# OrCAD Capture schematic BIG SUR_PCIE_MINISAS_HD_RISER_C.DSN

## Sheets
1 03.MINI SAS HD CONN: size C; title: Big Sur; rev: C; company: Quanta
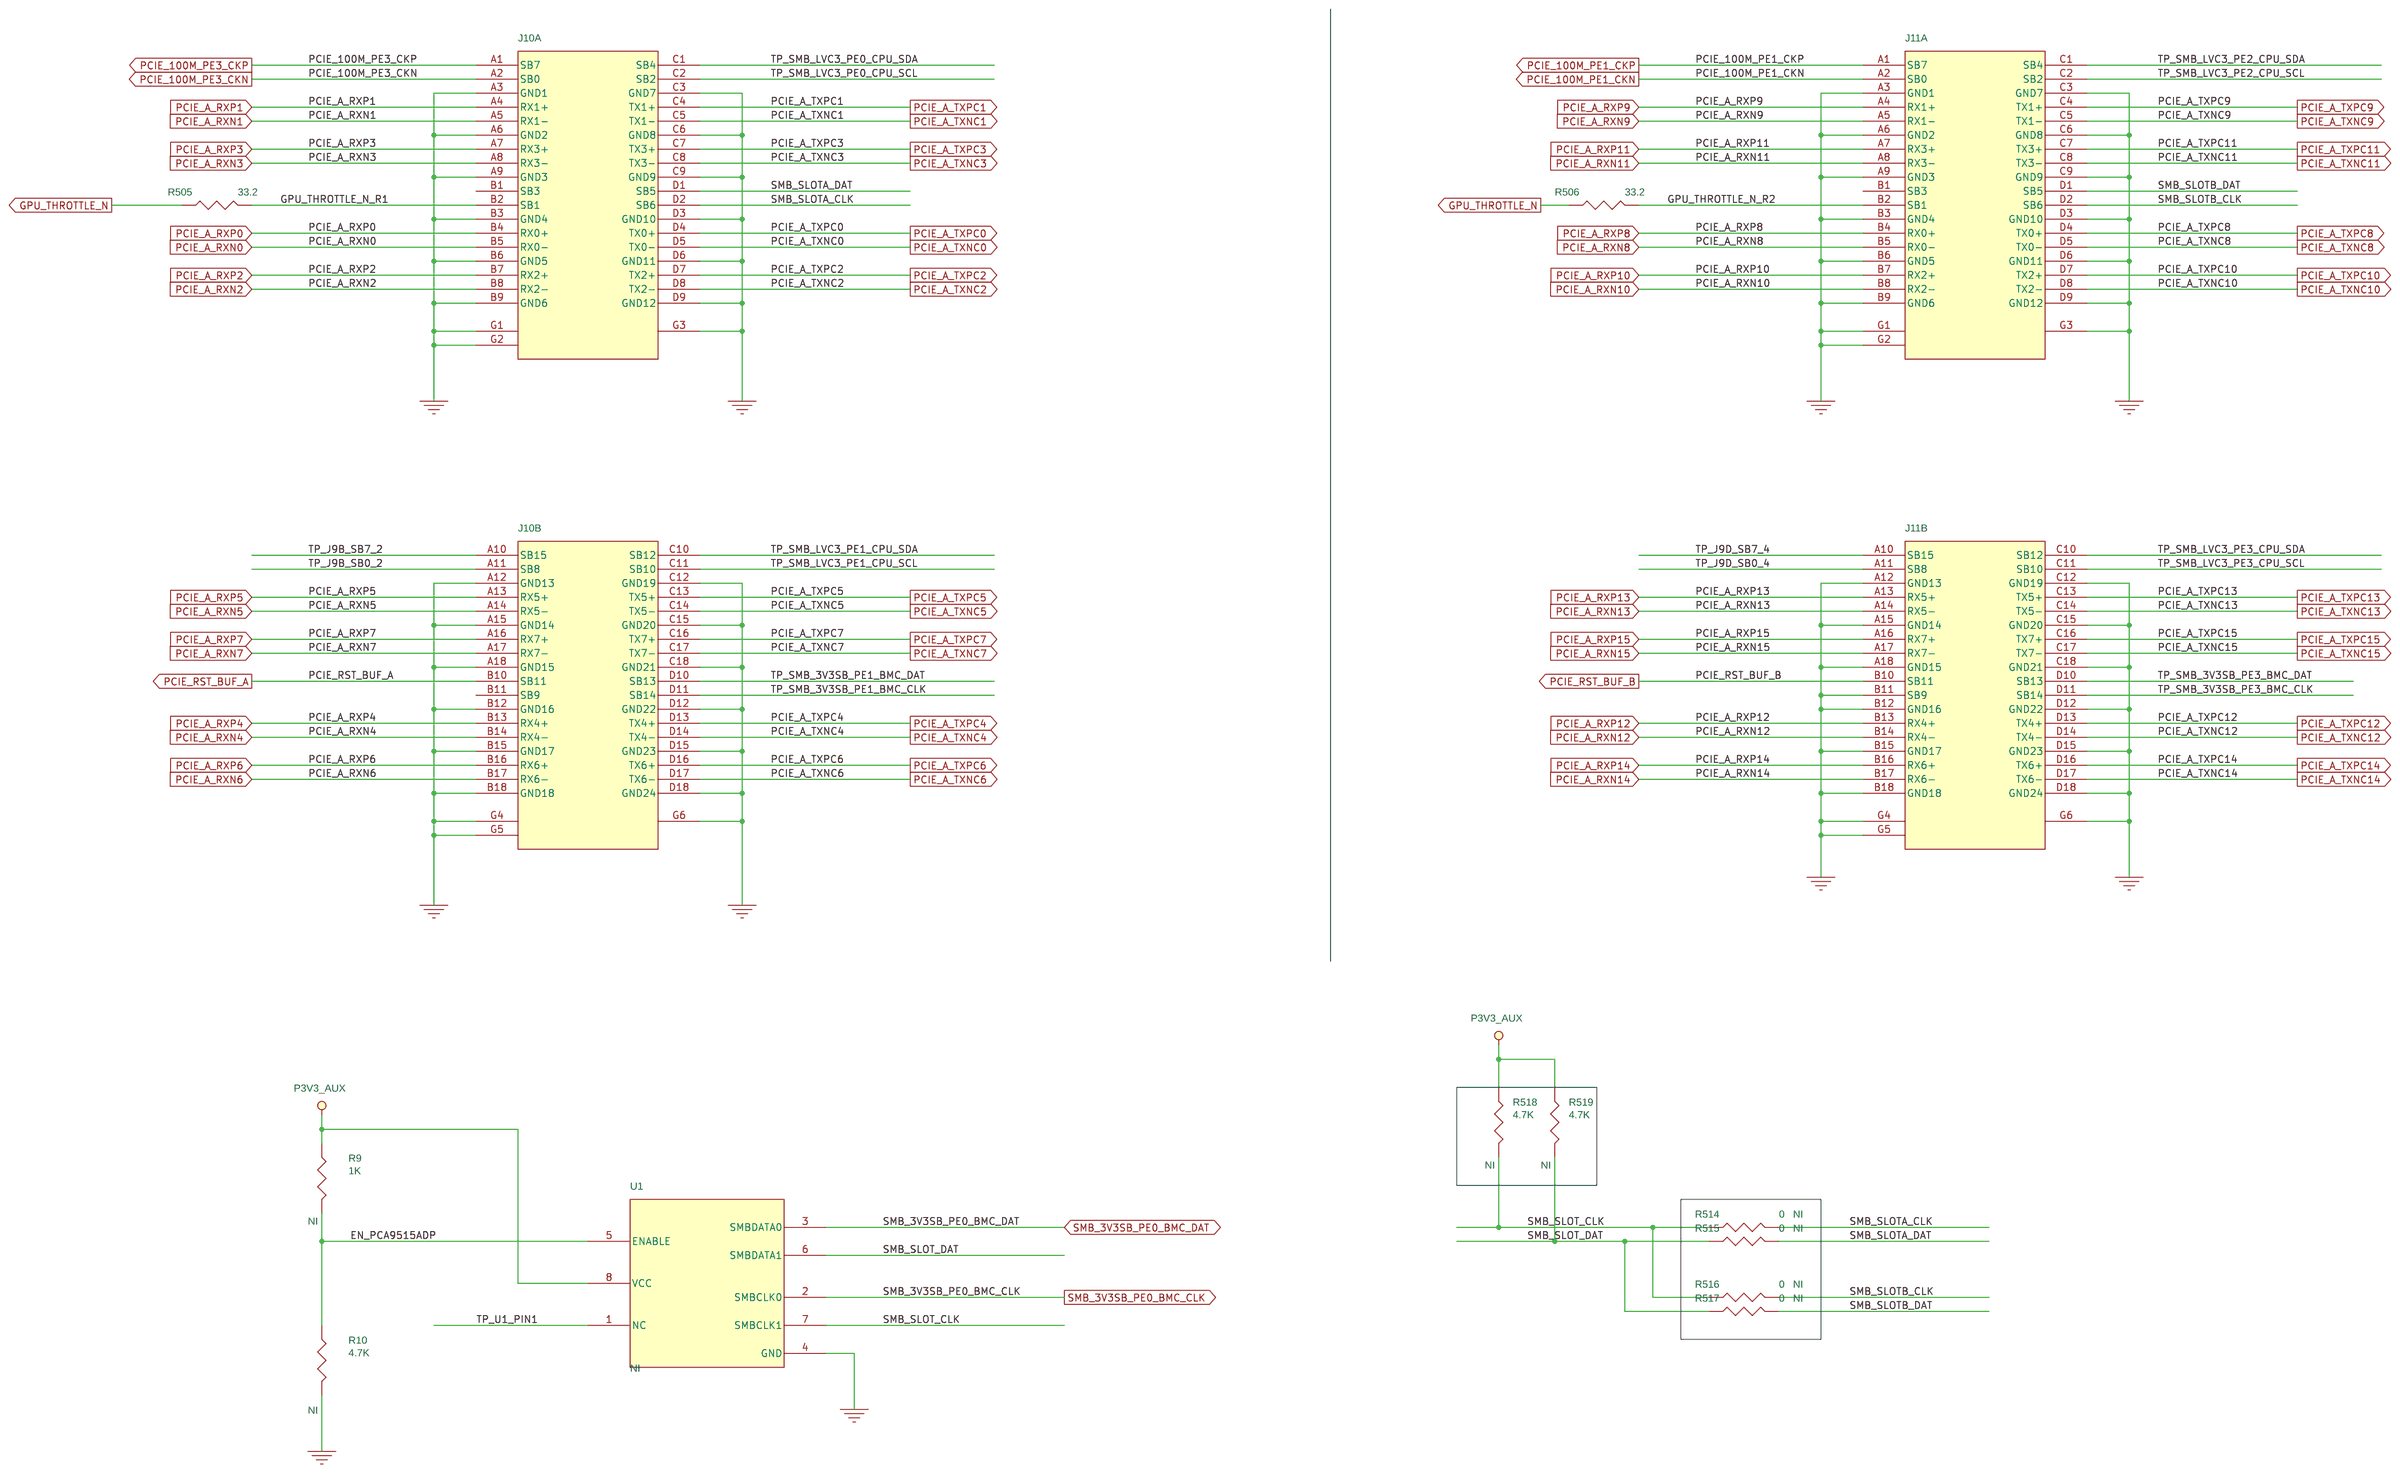
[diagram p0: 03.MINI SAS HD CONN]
2 01.Cover Page
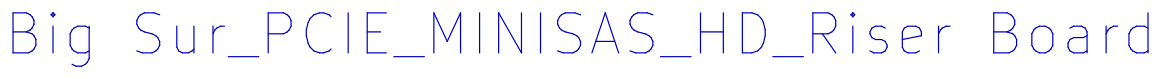
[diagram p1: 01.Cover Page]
3 02.PCIEX16 Golden Finger: size C
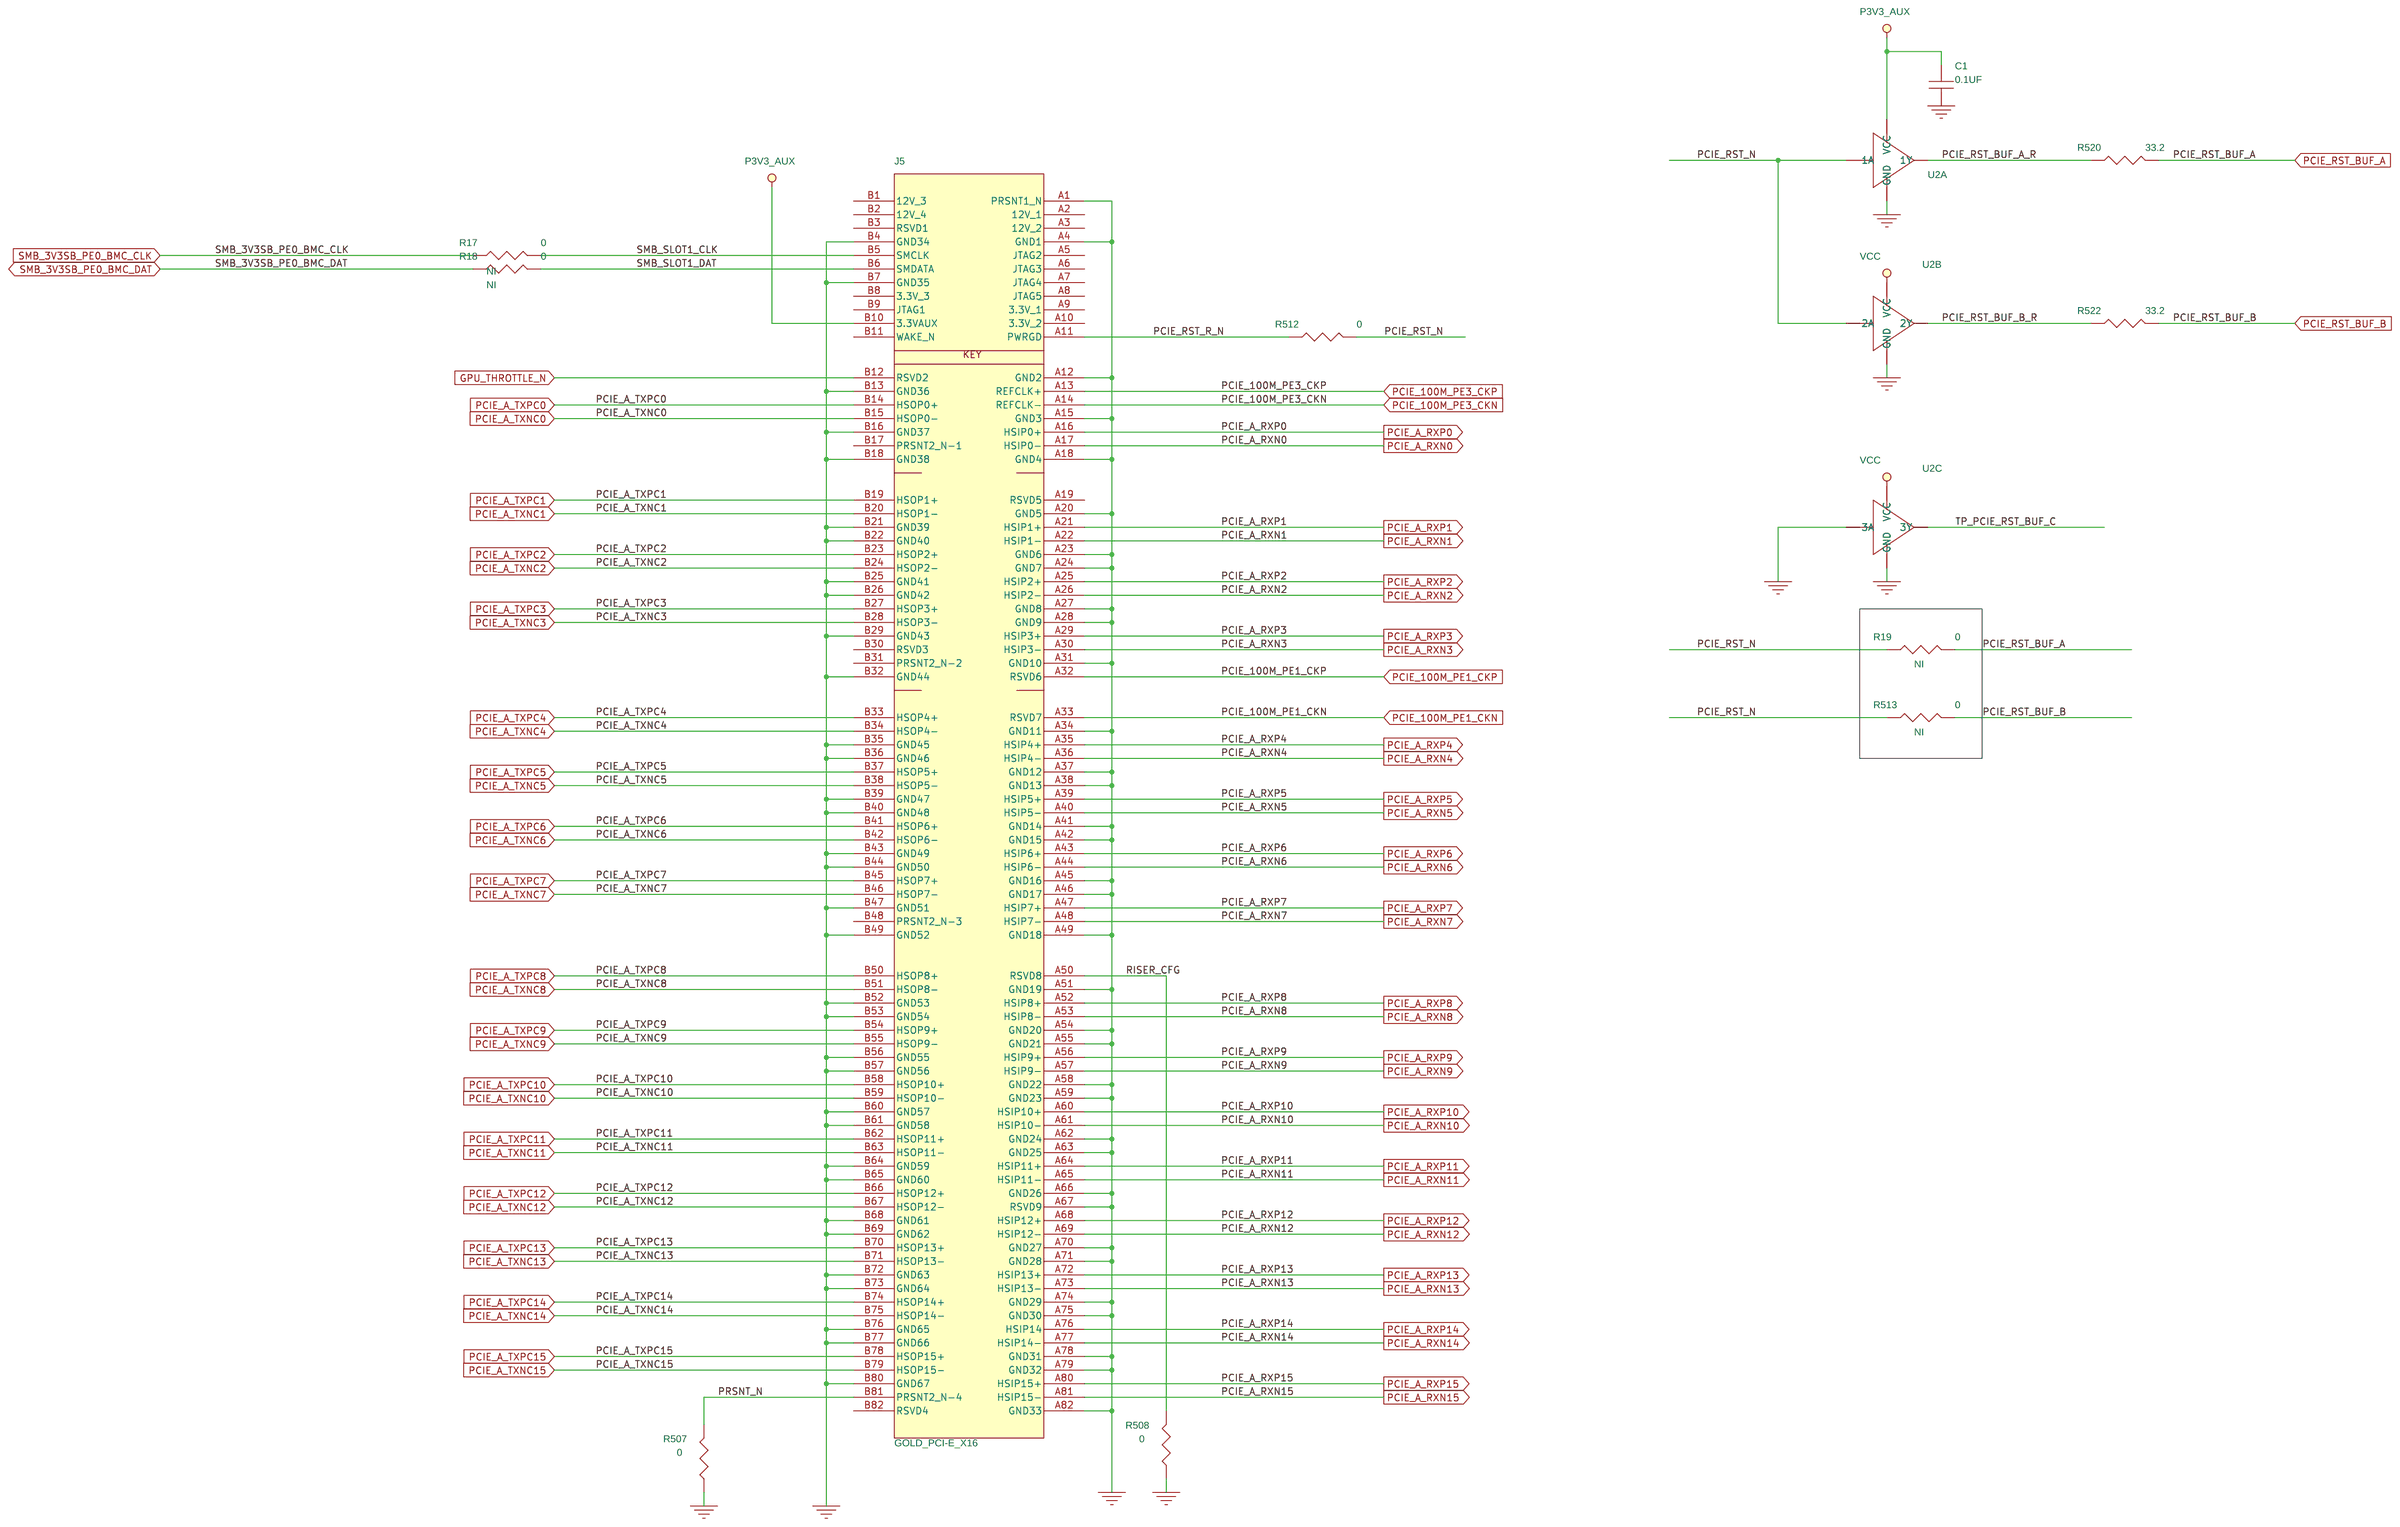
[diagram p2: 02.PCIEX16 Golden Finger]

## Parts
sheet 02.PCIEX16 Golden Finger
C1  0.1UF  [C0402]
J5  GOLD_PCI-E_X16  [GOLD_PCI-E_X16XB]
R17  0  [R0402]
R18  0  [R0402]
R19  0  [R0402]
R507  0  [R0402]
R508  0  [R0402]
R512  0  [R0402]
R513  0  [R0402]
R520  33.2  [R0402]
R522  33.2  [R0402]
U2  74LVC3G34  [SSOP8]  (sections A,B,C)
sheet 03.MINI SAS HD CONN
J10  CONN72  [CON_F72S4H8D_P0-75W3-53_LDHXA]  (sections A,B)
J11  CONN72  [CON_F72S4H8D_P0-75W3-53_LDHXA]  (sections A,B)
R9  1K  [R0402]
R10  4.7K  [R0402]
R505  33.2  [R0402]
R506  33.2  [R0402]
R514  0  [R0402]
R515  0  [R0402]
R516  0  [R0402]
R517  0  [R0402]
R518  4.7K  [R0402]
R519  4.7K  [R0402]
U1  PCA9515ADP  [TSSOP8_3]

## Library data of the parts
C1 = CAP_NP: Part_Type: *LF_C0402
J5 = PCI_EXPRESS_X16_CONN_1: Part_Type: Misc
R9 R10 R17-R19 R513-R519 = R: Not_insert: NI; Part_Type: *LF_Resistor; WATTAGE: 1/16W
R505-R508 R512 R520 R522 = R: Part_Type: *LF_Resistor; WATTAGE: 1/16W
U2 = 74LVC3G34: Part_Type: *LF_Chipset
J10 J11 = SCONN72_G40H2232212HRC: Part_Type: *LF_Connector
U1 = PCA9515: Not_insert: NI; Part_Type: Chipset

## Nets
3.3V_1: J5.A9(3.3V_1)
3.3V_2: J5.A10(3.3V_2)
3.3V_3: J5.B8(3.3V_3)
12V_1: J5.A2(12V_1)
12V_2: J5.A3(12V_2)
12V_3: J5.B1(12V_3)
12V_4: J5.B2(12V_4)
GND: C1.2 J5.A1(PRSNT1_N) J5.A4(GND1) J5.A12(GND2) J5.A15(GND3) J5.A18(GND4) J5.A20(GND5) J5.A23(GND6) J5.A24(GND7) J5.A27(GND8) J5.A28(GND9) J5.A31(GND10) J5.A34(GND11) J5.A37(GND12) J5.A38(GND13) J5.A41(GND14) J5.A42(GND15) J5.A45(GND16) J5.A46(GND17) J5.A49(GND18) J5.A51(GND19) J5.A54(GND20) J5.A55(GND21) J5.A58(GND22) J5.A59(GND23) J5.A62(GND24) J5.A63(GND25) J5.A66(GND26) J5.A67(RSVD9) J5.A70(GND27) J5.A71(GND28) J5.A74(GND29) J5.A75(GND30) J5.A78(GND31) J5.A79(GND32) J5.A82(GND33) J5.B4(GND34) J5.B7(GND35) J5.B13(GND36) J5.B16(GND37) J5.B18(GND38) J5.B21(GND39) J5.B22(GND40) J5.B25(GND41) J5.B26(GND42) J5.B29(GND43) J5.B32(GND44) J5.B35(GND45) J5.B36(GND46) J5.B39(GND47) J5.B40(GND48) J5.B43(GND49) J5.B44(GND50) J5.B47(GND51) J5.B49(GND52) J5.B52(GND53) J5.B53(GND54) J5.B56(GND55) J5.B57(GND56) J5.B60(GND57) J5.B61(GND58) J5.B64(GND59) J5.B65(GND60) J5.B68(GND61) J5.B69(GND62) J5.B72(GND63) J5.B73(GND64) J5.B76(GND65) J5.B77(GND66) J5.B80(GND67) J10.A3(GND1) J10.A6(GND2) J10.A9(GND3) J10.A12(GND13) J10.A15(GND14) J10.A18(GND15) J10.B3(GND4) J10.B6(GND5) J10.B9(GND6) J10.B12(GND16) J10.B15(GND17) J10.B18(GND18) J10.C3(GND7) J10.C6(GND8) J10.C9(GND9) J10.C12(GND19) J10.C15(GND20) J10.C18(GND21) J10.D3(GND10) J10.D6(GND11) J10.D9(GND12) J10.D12(GND22) J10.D15(GND23) J10.D18(GND24) J10.G1 J10.G2 J10.G3 J10.G4 J10.G5 J10.G6 J11.A3(GND1) J11.A6(GND2) J11.A9(GND3) J11.A12(GND13) J11.A15(GND14) J11.A18(GND15) J11.B3(GND4) J11.B6(GND5) J11.B9(GND6) J11.B11(SB9) J11.B12(GND16) J11.B15(GND17) J11.B18(GND18) J11.C3(GND7) J11.C6(GND8) J11.C9(GND9) J11.C12(GND19) J11.C15(GND20) J11.C18(GND21) J11.D3(GND10) J11.D6(GND11) J11.D9(GND12) J11.D12(GND22) J11.D15(GND23) J11.D18(GND24) J11.G1 J11.G2 J11.G3 J11.G4 J11.G5 J11.G6 R10.2 R507.1 R508.1 U1.4(GND) U2.4(GND) U2.6(3A)
P3V3_AUX: C1.1 J5.B10(3.3VAUX) R9.1 R518.1 R519.1 U1.8(VCC) U2.8(VCC)
EN_PCA9515ADP: R9.2 R10.1 U1.5(ENABLE)
GPU_THROTTLE_N: J5.B12(RSVD2) R505.1 R506.1
GPU_THROTTLE_N_R1: J10.B2(SB1) R505.2
GPU_THROTTLE_N_R2: J11.B2(SB1) R506.2
PCIE_100M_PE1_CKN: J5.A33(RSVD7) J11.A2(SB0)
PCIE_100M_PE1_CKP: J5.A32(RSVD6) J11.A1(SB7)
PCIE_100M_PE3_CKN: J5.A14(REFCLK-) J10.A2(SB0)
PCIE_100M_PE3_CKP: J5.A13(REFCLK+) J10.A1(SB7)
PCIE_A_RXN0: J5.A17(HSIP0-) J10.B5(RX0-)
PCIE_A_RXN1: J5.A22(HSIP1-) J10.A5(RX1-)
PCIE_A_RXN2: J5.A26(HSIP2-) J10.B8(RX2-)
PCIE_A_RXN3: J5.A30(HSIP3-) J10.A8(RX3-)
PCIE_A_RXN4: J5.A36(HSIP4-) J10.B14(RX4-)
PCIE_A_RXN5: J5.A40(HSIP5-) J10.A14(RX5-)
PCIE_A_RXN6: J5.A44(HSIP6-) J10.B17(RX6-)
PCIE_A_RXN7: J5.A48(HSIP7-) J10.A17(RX7-)
PCIE_A_RXN8: J5.A53(HSIP8-) J11.B5(RX0-)
PCIE_A_RXN9: J5.A57(HSIP9-) J11.A5(RX1-)
PCIE_A_RXN10: J5.A61(HSIP10-) J11.B8(RX2-)
PCIE_A_RXN11: J5.A65(HSIP11-) J11.A8(RX3-)
PCIE_A_RXN12: J5.A69(HSIP12-) J11.B14(RX4-)
PCIE_A_RXN13: J5.A73(HSIP13-) J11.A14(RX5-)
PCIE_A_RXN14: J5.A77(HSIP14-) J11.B17(RX6-)
PCIE_A_RXN15: J5.A81(HSIP15-) J11.A17(RX7-)
PCIE_A_RXP0: J5.A16(HSIP0+) J10.B4(RX0+)
PCIE_A_RXP1: J5.A21(HSIP1+) J10.A4(RX1+)
PCIE_A_RXP2: J5.A25(HSIP2+) J10.B7(RX2+)
PCIE_A_RXP3: J5.A29(HSIP3+) J10.A7(RX3+)
PCIE_A_RXP4: J5.A35(HSIP4+) J10.B13(RX4+)
PCIE_A_RXP5: J5.A39(HSIP5+) J10.A13(RX5+)
PCIE_A_RXP6: J5.A43(HSIP6+) J10.B16(RX6+)
PCIE_A_RXP7: J5.A47(HSIP7+) J10.A16(RX7+)
PCIE_A_RXP8: J5.A52(HSIP8+) J11.B4(RX0+)
PCIE_A_RXP9: J5.A56(HSIP9+) J11.A4(RX1+)
PCIE_A_RXP10: J5.A60(HSIP10+) J11.B7(RX2+)
PCIE_A_RXP11: J5.A64(HSIP11+) J11.A7(RX3+)
PCIE_A_RXP12: J5.A68(HSIP12+) J11.B13(RX4+)
PCIE_A_RXP13: J5.A72(HSIP13+) J11.A13(RX5+)
PCIE_A_RXP14: J5.A76(HSIP14) J11.B16(RX6+)
PCIE_A_RXP15: J5.A80(HSIP15+) J11.A16(RX7+)
PCIE_A_TXNC0: J5.B15(HSOP0-) J10.D5(TX0-)
PCIE_A_TXNC1: J5.B20(HSOP1-) J10.C5(TX1-)
PCIE_A_TXNC2: J5.B24(HSOP2-) J10.D8(TX2-)
PCIE_A_TXNC3: J5.B28(HSOP3-) J10.C8(TX3-)
PCIE_A_TXNC4: J5.B34(HSOP4-) J10.D14(TX4-)
PCIE_A_TXNC5: J5.B38(HSOP5-) J10.C14(TX5-)
PCIE_A_TXNC6: J5.B42(HSOP6-) J10.D17(TX6-)
PCIE_A_TXNC7: J5.B46(HSOP7-) J10.C17(TX7-)
PCIE_A_TXNC8: J5.B51(HSOP8-) J11.D5(TX0-)
PCIE_A_TXNC9: J5.B55(HSOP9-) J11.C5(TX1-)
PCIE_A_TXNC10: J5.B59(HSOP10-) J11.D8(TX2-)
PCIE_A_TXNC11: J5.B63(HSOP11-) J11.C8(TX3-)
PCIE_A_TXNC12: J5.B67(HSOP12-) J11.D14(TX4-)
PCIE_A_TXNC13: J5.B71(HSOP13-) J11.C14(TX5-)
PCIE_A_TXNC14: J5.B75(HSOP14-) J11.D17(TX6-)
PCIE_A_TXNC15: J5.B79(HSOP15-) J11.C17(TX7-)
PCIE_A_TXPC0: J5.B14(HSOP0+) J10.D4(TX0+)
PCIE_A_TXPC1: J5.B19(HSOP1+) J10.C4(TX1+)
PCIE_A_TXPC2: J5.B23(HSOP2+) J10.D7(TX2+)
PCIE_A_TXPC3: J5.B27(HSOP3+) J10.C7(TX3+)
PCIE_A_TXPC4: J5.B33(HSOP4+) J10.D13(TX4+)
PCIE_A_TXPC5: J5.B37(HSOP5+) J10.C13(TX5+)
PCIE_A_TXPC6: J5.B41(HSOP6+) J10.D16(TX6+)
PCIE_A_TXPC7: J5.B45(HSOP7+) J10.C16(TX7+)
PCIE_A_TXPC8: J5.B50(HSOP8+) J11.D4(TX0+)
PCIE_A_TXPC9: J5.B54(HSOP9+) J11.C4(TX1+)
PCIE_A_TXPC10: J5.B58(HSOP10+) J11.D7(TX2+)
PCIE_A_TXPC11: J5.B62(HSOP11+) J11.C7(TX3+)
PCIE_A_TXPC12: J5.B66(HSOP12+) J11.D13(TX4+)
PCIE_A_TXPC13: J5.B70(HSOP13+) J11.C13(TX5+)
PCIE_A_TXPC14: J5.B74(HSOP14+) J11.D16(TX6+)
PCIE_A_TXPC15: J5.B78(HSOP15+) J11.C16(TX7+)
PCIE_RST_BUF_A: J10.B10(SB11) R19.2 R520.2
PCIE_RST_BUF_A_R: R520.1 U2.7(1Y)
PCIE_RST_BUF_B: J11.B10(SB11) R513.2 R522.2
PCIE_RST_BUF_B_R: R522.1 U2.5(2Y)
PCIE_RST_N: R19.1 R512.2 R513.1 U2.1(1A) U2.3(2A)
PCIE_RST_R_N: J5.A11(PWRGD) R512.1
PRSNT_N: J5.B81(PRSNT2_N-4) R507.2
RISER_CFG: J5.A50(RSVD8) R508.2
SMB_3V3SB_PE0_BMC_CLK: R17.1 U1.2(SMBCLK0)
SMB_3V3SB_PE0_BMC_DAT: R18.1 U1.3(SMBDATA0)
SMB_SLOT1_CLK: J5.B5(SMCLK) R17.2
SMB_SLOT1_DAT: J5.B6(SMDATA) R18.2
SMB_SLOT_CLK: R514.1 R516.1 R518.2 U1.7(SMBCLK1)
SMB_SLOT_DAT: R515.1 R517.1 R519.2 U1.6(SMBDATA1)
SMB_SLOTA_CLK: J10.D2(SB6) R514.2
SMB_SLOTA_DAT: J10.D1(SB5) R515.2
SMB_SLOTB_CLK: J11.D2(SB6) R516.2
SMB_SLOTB_DAT: J11.D1(SB5) R517.2
TP_J9B_SB0_2: J10.A11(SB8)
TP_J9B_SB7_2: J10.A10(SB15)
TP_J9D_SB0_4: J11.A11(SB8)
TP_J9D_SB7_4: J11.A10(SB15)
TP_PCIE_RST_BUF_C: U2.2(3Y)
TP_SMB_3V3SB_PE1_BMC_CLK: J10.D11(SB14)
TP_SMB_3V3SB_PE1_BMC_DAT: J10.D10(SB13)
TP_SMB_3V3SB_PE3_BMC_CLK: J11.D11(SB14)
TP_SMB_3V3SB_PE3_BMC_DAT: J11.D10(SB13)
TP_SMB_LVC3_PE0_CPU_SCL: J10.C2(SB2)
TP_SMB_LVC3_PE0_CPU_SDA: J10.C1(SB4)
TP_SMB_LVC3_PE1_CPU_SCL: J10.C11(SB10)
TP_SMB_LVC3_PE1_CPU_SDA: J10.C10(SB12)
TP_SMB_LVC3_PE2_CPU_SCL: J11.C2(SB2)
TP_SMB_LVC3_PE2_CPU_SDA: J11.C1(SB4)
TP_SMB_LVC3_PE3_CPU_SCL: J11.C11(SB10)
TP_SMB_LVC3_PE3_CPU_SDA: J11.C10(SB12)
TP_U1_PIN1: U1.1(NC)

Not connected (* = marked no-connect by the designer): J5 A5(JTAG2) A6(JTAG3) A7(JTAG4) A8(JTAG5) A19(RSVD5) B3(RSVD1) B9(JTAG1) B11(WAKE_N) B17(PRSNT2_N-1) B30(RSVD3) B31(PRSNT2_N-2) B48(PRSNT2_N-3) B82(RSVD4); J10 B1(SB3) B11(SB9); J11 B1(SB3)

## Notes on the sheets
sheet 2
- Big Sur_PCIE_MINISAS_HD_Riser Board
